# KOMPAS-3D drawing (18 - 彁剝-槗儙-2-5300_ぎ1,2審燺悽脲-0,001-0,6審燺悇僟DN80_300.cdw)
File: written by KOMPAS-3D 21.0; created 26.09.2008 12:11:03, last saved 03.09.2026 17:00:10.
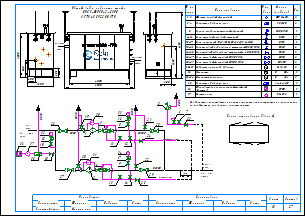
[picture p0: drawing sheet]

Sheets 1-2: A3, landscape

Document properties: Наименование: Макро:21; Автор: RaskoAdmin; Форматы листов документа: 2xA3; Полное имя файла: \\UR38nt01\Departments\КТО\КБ ПУРДГ\Заявки\Прайс-лист на типовые шкафы ГРПШ\ПРДГ_стандарт_20_03_2026\ПРДГ с РДГ(Н, В)\ПРДГ-ШУГО-2-5300_до1,2МПа_Рвых-0,001-0,6МПа_РДГ_DN80_300.cdw

Title block, sheet 1: Наименование: Пункт учета газа / ПУГ-Ш-400-Р / ЛГТИ.485922.001ТУ; designation: ЛГТИ.03.4411141; sheet number: 1; Количество листов документа: 2; organisation: ООО "ЭЛЬСТЕР Газэлектроника"; Форматы листов документа: A3; stored path: C:\Рабочие документы\Компас\ПУГ\Схема.cdw; Разработал: Устинов; Проверил: Кошкин; Утвердил: Кошкин
Title block, sheet 2: sheet number: 2; stored path: D:\Рабочие документы\Заявки\ПУРДГ\ПУРДГ-ШУЭО-2-100-Р 4411220.cdw; designation, second copy: ЛГТИ.03.4411141-

Views: Вид 1, Вид 2
Referenced files: wcvoit.frw
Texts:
  Normal
  Общий вид и габариты шкафа
  ПРДГ-ШУГО-2-5300
  DN300
  Выход газа
  DN80
  Вход газа
  logo-rasko-ge.png
  Вход
  газа
  PDI
  Выход
  Р=     кПа
  DN50
  DN25
  DN20
  Импульс DN20
  ≥5DN
  HYSWLongFangSong
  Р=       МПа
  № на
  схеме
  Усл.
  обозн.
  Марка
  (модель)
  Кол.
  Фильтр газовый фланцевый
  ФГ 16-80
  Регулятор давления газа
  РДГ-50
  Клапан предохранительный сбросной
  КПС DN20
  Кран шаровой газовый латунный
  DN15
  Кран кнопочный VE-РАСКО-НЗ-1,6-G1/2-М20
  Кран шаровой "под приварку" штуцерный DN20 PN16
  Кран шаровой "под приварку" штуцерный п/п DN20 PN16
  Кран шаровой фланцевый DN80 PN16
  Кран шаровой фланцевый DN300 PN16
  Индикатор перепада давления
  Delta 15
  Манометр
  Манометр-напоромер
  0...     МПа
  0...     кПа
  Обогреватель газогорелочный шкафной
  (Эльтон")
  Счетчик газа
  Venio-A-15
  ОГШН
  BK-G1,6
  Схема открывания дверей
  Предприятие изготовитель может заменять комплектующие на аналогичные,
  не ухудшающие заявленных характеристик.
  Должность
  Конструктор
  Фамилия
  Подпись
  Дата
  Согласовано
  Максимкин
  Лист
  Листов
  POLYLINE_STYLE_0.18_RGB_0_0_0
  POLYLINE_STYLE_0.50_RGB_0_0_0
  POLYLINE_STYLE_0.34_RGB_0_0_0
  PHANTOM_RGB_0_0_0_SC_1_THICK_0.18
  K5LT_THIN_RGB_0_0_0_THICK_0.18
  K5LT32769_RGB_0_0_0_THICK_0.18
  K5LT12_RGB_0_0_0_SC_1_THICK_0.18
  K5LT_DASHED_RGB_0_0_0_SC_1_THICK_0.18
  ACISOTGL_RGB_0_0_0_SC_0.8_THICK_0.25
  CONTINUOUS_RGB_0_127_31_THICK_0.3
  CONTINUOUS_RGB_0_0_255_THICK_0.35
  CONTINUOUS_RGB_255_0_0_THICK_0.35
  POLYLINE_STYLE_0.25_RGB_0_0_0
  CONTINUOUS_RGB_0_0_0_THICK_0.5
  POLYLINE_STYLE_0.35_RGB_0_0_255
  CONTINUOUS_RGB_0_0_0_THICK_0.4
  CONTINUOUS_RGB_0_0_0_THICK_0.35
  Без оформления
Dimensions and other numbers on the sheet: 1; 600; 1200; 500; 305; 2000; 4300; 1300; 4130; 4000; 2; 3; 4; 5; 10; 27; 28; 29; 23; 8; 12; 19; 20; 21; 22; 25; 24; 30; 31; 15; 16; 32; 26; 6; 7; 11; 14; 13; 33; 9; 17; 34; 18; 35; 36; 37; 1, 2; 3, 4; 6-14; 15-17; 18-23; 24-25; 26-27; 28-29; 30-31; 33-34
